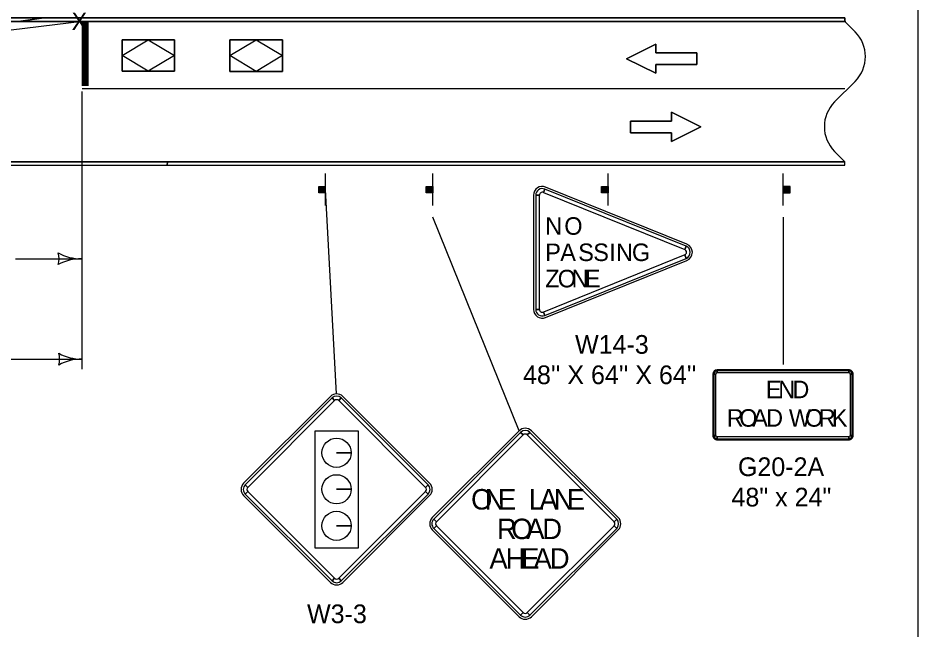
# Model space of a CAD drawing. Extents: x -2134934 to -2122394, y -2140205 to -2137036.
# Drawn here: x -2132569 to -2131799, y -2138065 to -2137542 of the extents above; entities that cross this region are included whole.
import ezdxf

# ---------------------------------------------------------------- set-up
doc = ezdxf.new("R2010")
doc.units = 0
for name, color, linetype in [('Barrier', 7, 'Continuous'), ('BridgeSuperStructureExisting', 7, 'Continuous'), ('Default', 7, 'Continuous'), ('DsnShtPlotIdentification', 7, 'Continuous'), ('DsnShtPlotShape', 7, 'Continuous'), ('dsnTextFinalPlan', 7, 'Continuous')]:
    doc.layers.add(name, color=color, linetype=linetype)

msp = doc.modelspace()

# ---------------------------------------------------------------- linework, layer by layer
at = {"layer": 'Barrier'}
for p, q in [((-2132119.84, -2137691.45), (-2132118.67, -2137688.56)), ((-2131997.15, -2137735.69), (-2132117.97, -2137686.82)), ((-2132128.28, -2137693.77), (-2132128.28, -2137791.52)), ((-2132126.41, -2137693.77), (-2132123.28, -2137693.77)), ((-2131997.85, -2137737.43), (-2131999.02, -2137740.33)), ((-2132117.97, -2137798.48), (-2131997.15, -2137749.6)), ((-2131999.02, -2137744.96), (-2131997.85, -2137747.86)), ((-2132123.28, -2137791.52), (-2132126.41, -2137791.52)), ((-2132118.67, -2137796.74), (-2132119.84, -2137793.84)), ((-2131858.66, -2137843.14), (-2131971.16, -2137843.14)), ((-2131971.16, -2137845.64), (-2131971.16, -2137844.08)), ((-2131858.66, -2137844.08), (-2131858.66, -2137845.64)), ((-2131974.91, -2137846.89), (-2131974.91, -2137899.39)), ((-2131973.97, -2137846.89), (-2131972.41, -2137846.89)), ((-2131857.41, -2137846.89), (-2131855.85, -2137846.89)), ((-2131854.91, -2137899.39), (-2131854.91, -2137846.89)), ((-2132301.99, -2137865.99), (-2132376.24, -2137940.23)), ((-2132300.66, -2137867.31), (-2132298.45, -2137869.52)), ((-2132294.92, -2137869.52), (-2132292.71, -2137867.31)), ((-2132217.14, -2137940.23), (-2132291.38, -2137865.99)), ((-2132140.68, -2137895.4), (-2132214.93, -2137969.64)), ((-2132139.36, -2137896.72), (-2132137.15, -2137898.93)), ((-2132133.61, -2137898.93), (-2132131.4, -2137896.72)), ((-2132055.83, -2137969.64), (-2132130.08, -2137895.4)), ((-2131972.41, -2137899.39), (-2131973.97, -2137899.39)), ((-2131971.16, -2137902.2), (-2131971.16, -2137900.64)), ((-2131971.16, -2137903.14), (-2131858.66, -2137903.14)), ((-2131858.66, -2137900.64), (-2131858.66, -2137902.2)), ((-2131855.85, -2137899.39), (-2131857.41, -2137899.39)), ((-2132284.28, -2137914.21), (-2132296.78, -2137914.21)), ((-2132296.78, -2137914.21), (-2132284.28, -2137914.21)), ((-2132372.7, -2137943.77), (-2132374.91, -2137941.56)), ((-2132218.46, -2137941.56), (-2132220.67, -2137943.77)), ((-2132376.24, -2137950.84), (-2132301.99, -2138025.09)), ((-2132374.91, -2137949.51), (-2132372.7, -2137947.3)), ((-2132284.28, -2137945.46), (-2132296.78, -2137945.46)), ((-2132296.78, -2137945.46), (-2132284.28, -2137945.46)), ((-2132291.38, -2138025.09), (-2132217.14, -2137950.84)), ((-2132220.67, -2137947.3), (-2132218.46, -2137949.51)), ((-2132211.4, -2137973.18), (-2132213.6, -2137970.97)), ((-2132057.16, -2137970.97), (-2132059.37, -2137973.18)), ((-2132284.28, -2137976.71), (-2132296.78, -2137976.71)), ((-2132296.78, -2137976.71), (-2132284.28, -2137976.71)), ((-2132214.93, -2137980.25), (-2132140.68, -2138054.5)), ((-2132213.6, -2137978.92), (-2132211.4, -2137976.71)), ((-2132130.08, -2138054.5), (-2132055.83, -2137980.25)), ((-2132059.37, -2137976.71), (-2132057.16, -2137978.92)), ((-2132298.45, -2138021.55), (-2132300.66, -2138023.76)), ((-2132292.71, -2138023.76), (-2132294.92, -2138021.55)), ((-2132137.15, -2138050.96), (-2132139.36, -2138053.17)), ((-2132131.4, -2138053.17), (-2132133.61, -2138050.96))]:
    msp.add_line(p, q, dxfattribs=at)
for points in [[(-2131997.85, -2137737.43), (-2132118.67, -2137688.56), (-2132119.84, -2137691.45), (-2131999.02, -2137740.33), (-2131997.85, -2137737.43)], [(-2132126.41, -2137693.77), (-2132126.41, -2137791.52), (-2132123.28, -2137791.52), (-2132123.28, -2137693.77), (-2132126.41, -2137693.77)], [(-2132118.67, -2137796.74), (-2131997.85, -2137747.86), (-2131999.02, -2137744.96), (-2132119.84, -2137793.84), (-2132118.67, -2137796.74)], [(-2131858.66, -2137844.08), (-2131971.16, -2137844.08), (-2131971.16, -2137845.64), (-2131858.66, -2137845.64), (-2131858.66, -2137844.08)], [(-2131973.97, -2137846.89), (-2131973.97, -2137899.39), (-2131972.41, -2137899.39), (-2131972.41, -2137846.89), (-2131973.97, -2137846.89)], [(-2131855.85, -2137899.39), (-2131855.85, -2137846.89), (-2131857.41, -2137846.89), (-2131857.41, -2137899.39), (-2131855.85, -2137899.39)], [(-2132300.66, -2137867.31), (-2132374.91, -2137941.56), (-2132372.7, -2137943.77), (-2132298.45, -2137869.52), (-2132300.66, -2137867.31)], [(-2132218.46, -2137941.56), (-2132292.71, -2137867.31), (-2132294.92, -2137869.52), (-2132220.67, -2137943.77), (-2132218.46, -2137941.56)], [(-2132277.96, -2137895.59), (-2132315.42, -2137895.59), (-2132315.42, -2137995.48), (-2132277.96, -2137995.48), (-2132277.96, -2137895.59)], [(-2132139.36, -2137896.72), (-2132213.6, -2137970.97), (-2132211.4, -2137973.18), (-2132137.15, -2137898.93), (-2132139.36, -2137896.72)], [(-2132057.16, -2137970.97), (-2132131.4, -2137896.72), (-2132133.61, -2137898.93), (-2132059.37, -2137973.18), (-2132057.16, -2137970.97)], [(-2131971.16, -2137902.2), (-2131858.66, -2137902.2), (-2131858.66, -2137900.64), (-2131971.16, -2137900.64), (-2131971.16, -2137902.2)], [(-2132374.91, -2137949.51), (-2132300.66, -2138023.76), (-2132298.45, -2138021.55), (-2132372.7, -2137947.3), (-2132374.91, -2137949.51)], [(-2132292.71, -2138023.76), (-2132218.46, -2137949.51), (-2132220.67, -2137947.3), (-2132294.92, -2138021.55), (-2132292.71, -2138023.76)], [(-2132213.6, -2137978.92), (-2132139.36, -2138053.17), (-2132137.15, -2138050.96), (-2132211.4, -2137976.71), (-2132213.6, -2137978.92)], [(-2132131.4, -2138053.17), (-2132057.16, -2137978.92), (-2132059.37, -2137976.71), (-2132133.61, -2138050.96), (-2132131.4, -2138053.17)]]:
    msp.add_lwpolyline(points, close=True, dxfattribs=at)
for centre in [(-2132296.78, -2137914.21), (-2132296.78, -2137945.46), (-2132296.78, -2137976.71)]:
    msp.add_circle(centre, 12.5, dxfattribs=at)
for centre, radius, start, end in [((-2132120.78, -2137693.77), 7.5, 67.97571, 179.99985), ((-2132120.78, -2137693.77), 5.62, 67.97571, 179.99985), ((-2132120.78, -2137693.77), 2.5, 67.97571, 179.99985), ((-2131999.96, -2137742.65), 7.5, 292.02456, 67.97598), ((-2131999.96, -2137742.65), 2.5, 292.02456, 67.97541), ((-2131999.96, -2137742.65), 5.62, 292.02456, 67.97541), ((-2132120.78, -2137791.52), 7.5, 179.99985, 292.02456), ((-2132120.78, -2137791.52), 5.62, 179.99985, 292.02456), ((-2132120.78, -2137791.52), 2.5, 179.99985, 292.02456), ((-2131971.16, -2137846.89), 3.75, 90.00021, 179.99985), ((-2131971.16, -2137846.89), 2.81, 90.00021, 179.99985), ((-2131858.66, -2137846.89), 3.75, 0, 90.00021), ((-2131858.66, -2137846.89), 2.81, 0, 90.00021), ((-2131971.16, -2137846.89), 1.25, 90.00021, 179.99985), ((-2131858.66, -2137846.89), 1.25, 0, 90.00021), ((-2132296.69, -2137871.29), 7.5, 44.99999, 134.99974), ((-2132296.69, -2137871.29), 5.62, 44.99999, 134.99974), ((-2132296.69, -2137871.29), 2.5, 44.99999, 134.99974), ((-2132135.38, -2137900.7), 7.5, 44.99999, 134.99974), ((-2132135.38, -2137900.7), 5.62, 44.99999, 134.99974), ((-2132135.38, -2137900.7), 2.5, 44.99999, 134.99974), ((-2131971.16, -2137899.39), 3.75, 179.99985, 270.00006), ((-2131971.16, -2137899.39), 2.81, 179.99985, 270.00006), ((-2131971.16, -2137899.39), 1.25, 179.99985, 270.00006), ((-2131858.66, -2137899.39), 3.75, 270.00006, 0.00027), ((-2131858.66, -2137899.39), 2.81, 270.00006, 0.00027), ((-2131858.66, -2137899.39), 1.25, 270.00006, 0.00027), ((-2132370.93, -2137945.54), 7.5, 134.99974, 224.99995), ((-2132370.93, -2137945.54), 5.62, 134.99974, 224.99995), ((-2132370.93, -2137945.54), 2.5, 134.99974, 224.99995), ((-2132222.44, -2137945.54), 2.5, 315.00016, 44.9998), ((-2132222.44, -2137945.54), 5.62, 315.00016, 44.9998), ((-2132222.44, -2137945.54), 7.5, 315.00016, 44.9998), ((-2132209.63, -2137974.95), 7.5, 134.99974, 224.99995), ((-2132209.63, -2137974.95), 5.62, 134.99974, 224.99995), ((-2132209.63, -2137974.95), 2.5, 134.99974, 224.99995), ((-2132061.14, -2137974.95), 2.5, 315.00016, 44.9998), ((-2132061.14, -2137974.95), 5.62, 315.00016, 44.9998), ((-2132061.14, -2137974.95), 7.5, 315.00016, 44.9998), ((-2132296.69, -2138019.78), 7.5, 224.99995, 315.00016), ((-2132296.69, -2138019.78), 5.62, 224.99995, 315.00016), ((-2132296.69, -2138019.78), 2.5, 224.99995, 315.00016), ((-2132135.38, -2138049.19), 2.5, 224.99995, 315.00016), ((-2132135.38, -2138049.19), 7.5, 224.99995, 315.00016), ((-2132135.38, -2138049.19), 5.62, 224.99995, 315.00016)]:
    msp.add_arc(centre, radius, start, end, dxfattribs=at)
at = {"layer": 'BridgeSuperStructureExisting'}
for p, q in [((-2131861.99, -2137545.16), (-2133174.44, -2137545.16)), ((-2132514.45, -2137545.16), (-2133004.39, -2137605.15)), ((-2132514.45, -2137545.16), (-2132514.45, -2137600.16)), ((-2132513.45, -2137545.16), (-2132513.45, -2137600.16)), ((-2132512.45, -2137545.16), (-2132512.45, -2137600.16)), ((-2132511.45, -2137545.16), (-2132511.45, -2137600.16)), ((-2132510.45, -2137545.16), (-2132510.45, -2137600.16)), ((-2132509.45, -2137545.16), (-2132509.45, -2137600.16)), ((-2131853.21, -2137553.94), (-2131861.99, -2137545.16)), ((-2131853.2, -2137553.95), (-2131861.99, -2137545.16)), ((-2132480.28, -2137587.78), (-2132480.28, -2137560.78)), ((-2132480.28, -2137560.78), (-2132435.28, -2137560.78)), ((-2132480.28, -2137587.78), (-2132480.28, -2137560.78)), ((-2132480.28, -2137560.78), (-2132435.28, -2137560.78)), ((-2132435.28, -2137560.78), (-2132480.28, -2137560.78)), ((-2132480.28, -2137560.78), (-2132480.28, -2137587.78)), ((-2132435.28, -2137587.78), (-2132435.28, -2137560.78)), ((-2132435.28, -2137560.78), (-2132435.28, -2137587.78)), ((-2132435.28, -2137587.78), (-2132435.28, -2137560.78)), ((-2132388.09, -2137587.86), (-2132388.09, -2137560.86)), ((-2132388.09, -2137560.86), (-2132343.09, -2137560.86)), ((-2132388.09, -2137587.86), (-2132388.09, -2137560.86)), ((-2132388.09, -2137560.86), (-2132343.09, -2137560.86)), ((-2132343.09, -2137560.86), (-2132388.09, -2137560.86)), ((-2132388.09, -2137560.86), (-2132388.09, -2137587.86)), ((-2132343.09, -2137587.86), (-2132343.09, -2137560.86)), ((-2132343.09, -2137560.86), (-2132343.09, -2137587.86)), ((-2132343.09, -2137587.86), (-2132343.09, -2137560.86)), ((-2132480.28, -2137587.78), (-2132435.28, -2137587.78)), ((-2132435.28, -2137587.78), (-2132480.28, -2137587.78)), ((-2132480.28, -2137587.78), (-2132435.28, -2137587.78)), ((-2132388.09, -2137587.86), (-2132343.09, -2137587.86)), ((-2132343.09, -2137587.86), (-2132388.09, -2137587.86)), ((-2132388.09, -2137587.86), (-2132343.09, -2137587.86)), ((-2131870.78, -2137613.94), (-2131853.21, -2137596.37)), ((-2131870.78, -2137613.95), (-2131853.2, -2137596.37)), ((-2132514.45, -2137842.77), (-2132514.45, -2137605.16)), ((-2131861.99, -2137665.16), (-2131870.78, -2137656.37)), ((-2131861.99, -2137665.16), (-2131870.78, -2137656.37)), ((-2133364.44, -2137665.16), (-2131861.99, -2137665.16)), ((-2132306.28, -2137702.66), (-2132306.28, -2137675.16)), ((-2132214.45, -2137702.66), (-2132214.45, -2137675.16)), ((-2132064.45, -2137702.66), (-2132064.45, -2137675.16)), ((-2131914.64, -2137702.66), (-2131914.64, -2137675.16)), ((-2132311.61, -2137691.8), (-2132311.61, -2137686.21)), ((-2132311.29, -2137686.21), (-2132311.29, -2137691.8)), ((-2132311.07, -2137691.8), (-2132311.07, -2137686.21)), ((-2132310.75, -2137686.21), (-2132310.75, -2137691.8)), ((-2132310.52, -2137691.8), (-2132310.54, -2137686.21)), ((-2132310.11, -2137686.21), (-2132310.09, -2137691.8)), ((-2132309.89, -2137691.8), (-2132309.89, -2137686.21)), ((-2132309.45, -2137686.21), (-2132309.45, -2137691.8)), ((-2132309.08, -2137691.8), (-2132309.08, -2137686.21)), ((-2132308.76, -2137686.21), (-2132308.74, -2137691.8)), ((-2132308.54, -2137691.8), (-2132308.54, -2137686.21)), ((-2132308.27, -2137686.21), (-2132308.27, -2137691.8)), ((-2132307.94, -2137691.8), (-2132307.94, -2137686.21)), ((-2132307.73, -2137686.21), (-2132307.73, -2137691.8)), ((-2132307.5, -2137691.8), (-2132307.5, -2137686.21)), ((-2132307.24, -2137686.21), (-2132307.24, -2137691.8)), ((-2132306.98, -2137691.8), (-2132306.98, -2137686.21)), ((-2132306.7, -2137686.21), (-2132306.7, -2137691.8)), ((-2132296.69, -2137863.79), (-2132306.28, -2137688.91)), ((-2132219.77, -2137691.8), (-2132219.77, -2137686.21)), ((-2132219.45, -2137686.21), (-2132219.45, -2137691.8)), ((-2132219.23, -2137691.8), (-2132219.23, -2137686.21)), ((-2132218.91, -2137686.21), (-2132218.91, -2137691.8)), ((-2132218.69, -2137691.8), (-2132218.7, -2137686.21)), ((-2132218.27, -2137686.21), (-2132218.25, -2137691.8)), ((-2132218.05, -2137691.8), (-2132218.05, -2137686.21)), ((-2132217.62, -2137686.21), (-2132217.62, -2137691.8)), ((-2132217.24, -2137691.8), (-2132217.24, -2137686.21)), ((-2132216.92, -2137686.21), (-2132216.9, -2137691.8)), ((-2132216.7, -2137691.8), (-2132216.7, -2137686.21)), ((-2132216.43, -2137686.21), (-2132216.43, -2137691.8)), ((-2132216.1, -2137691.8), (-2132216.1, -2137686.21)), ((-2132215.89, -2137686.21), (-2132215.89, -2137691.8)), ((-2132215.67, -2137691.8), (-2132215.67, -2137686.21)), ((-2132215.4, -2137686.21), (-2132215.4, -2137691.8)), ((-2132215.14, -2137691.8), (-2132215.14, -2137686.21)), ((-2132214.86, -2137686.21), (-2132214.86, -2137691.8)), ((-2132069.77, -2137691.8), (-2132069.77, -2137686.21)), ((-2132069.45, -2137686.21), (-2132069.45, -2137691.8)), ((-2132069.23, -2137691.8), (-2132069.23, -2137686.21)), ((-2132068.91, -2137686.21), (-2132068.91, -2137691.8)), ((-2132068.69, -2137691.8), (-2132068.7, -2137686.21)), ((-2132068.27, -2137686.21), (-2132068.25, -2137691.8)), ((-2132068.05, -2137691.8), (-2132068.05, -2137686.21)), ((-2132067.62, -2137686.21), (-2132067.62, -2137691.8)), ((-2132067.24, -2137691.8), (-2132067.24, -2137686.21)), ((-2132066.92, -2137686.21), (-2132066.9, -2137691.8)), ((-2132066.7, -2137691.8), (-2132066.7, -2137686.21)), ((-2132066.43, -2137686.21), (-2132066.43, -2137691.8)), ((-2132066.1, -2137691.8), (-2132066.1, -2137686.21)), ((-2132065.89, -2137686.21), (-2132065.89, -2137691.8)), ((-2132065.67, -2137691.8), (-2132065.67, -2137686.21)), ((-2132065.4, -2137686.21), (-2132065.4, -2137691.8)), ((-2132065.14, -2137691.8), (-2132065.14, -2137686.21)), ((-2132064.86, -2137686.21), (-2132064.86, -2137691.8)), ((-2131914.22, -2137686.21), (-2131914.22, -2137691.8)), ((-2131913.94, -2137691.8), (-2131913.94, -2137686.21)), ((-2131913.68, -2137686.21), (-2131913.68, -2137691.8)), ((-2131913.42, -2137691.8), (-2131913.42, -2137686.21)), ((-2131913.19, -2137686.21), (-2131913.19, -2137691.8)), ((-2131912.99, -2137691.8), (-2131912.99, -2137686.21)), ((-2131912.65, -2137686.21), (-2131912.65, -2137691.8)), ((-2131912.39, -2137691.8), (-2131912.39, -2137686.21)), ((-2131912.16, -2137686.21), (-2131912.18, -2137691.8)), ((-2131911.84, -2137691.8), (-2131911.84, -2137686.21)), ((-2131911.47, -2137686.21), (-2131911.47, -2137691.8)), ((-2131911.04, -2137691.8), (-2131911.04, -2137686.21)), ((-2131910.81, -2137686.21), (-2131910.83, -2137691.8)), ((-2131910.4, -2137691.8), (-2131910.38, -2137686.21)), ((-2131910.17, -2137686.21), (-2131910.17, -2137691.8)), ((-2131909.85, -2137691.8), (-2131909.85, -2137686.21)), ((-2131909.63, -2137686.21), (-2131909.63, -2137691.8)), ((-2131909.31, -2137691.8), (-2131909.31, -2137686.21)), ((-2132140.68, -2137895.4), (-2132214.45, -2137712.66)), ((-2131914.45, -2137838.71), (-2131914.45, -2137712.66)), ((-2132571.38, -2137748.23), (-2132514.94, -2137748.23)), ((-2132739.17, -2137834.09), (-2132514.45, -2137834.09))]:
    msp.add_line(p, q, dxfattribs=at)
for points in [[(-2131988.74, -2137582), (-2131988.74, -2137572), (-2132023.74, -2137572), (-2132023.74, -2137564.5), (-2132048.74, -2137577), (-2132023.74, -2137589.5), (-2132023.74, -2137582)], [(-2132045.26, -2137630.33), (-2132045.26, -2137640.33), (-2132010.26, -2137640.33), (-2132010.26, -2137647.83), (-2131985.26, -2137635.33), (-2132010.26, -2137622.83), (-2132010.26, -2137630.33)], [(-2132306.38, -2137686.21), (-2132306.38, -2137691.84), (-2132312, -2137691.84), (-2132312, -2137686.21)], [(-2132214.54, -2137686.21), (-2132214.54, -2137691.84), (-2132220.17, -2137691.84), (-2132220.17, -2137686.21)], [(-2132064.54, -2137686.21), (-2132064.54, -2137691.84), (-2132070.17, -2137691.84), (-2132070.17, -2137686.21)], [(-2131914.54, -2137686.21), (-2131914.54, -2137691.84), (-2131908.92, -2137691.84), (-2131908.92, -2137686.21)]]:
    msp.add_lwpolyline(points, close=True, dxfattribs=at)
for points in [[(-2132023.74, -2137582), (-2132023.74, -2137589.5), (-2132048.74, -2137577), (-2132023.74, -2137564.5), (-2132023.74, -2137572), (-2131988.74, -2137572), (-2131988.74, -2137582), (-2132023.74, -2137582)], [(-2132010.26, -2137630.33), (-2132010.26, -2137622.83), (-2131985.26, -2137635.33), (-2132010.26, -2137647.83), (-2132010.26, -2137640.33), (-2132045.26, -2137640.33), (-2132045.26, -2137630.33), (-2132010.26, -2137630.33)]]:
    msp.add_lwpolyline(points, dxfattribs=at)
for centre, radius, start, end in [((-2131874.42, -2137575.16), 30, 315, 45), ((-2131874.42, -2137575.16), 30, 315, 45), ((-2131849.56, -2137635.16), 30, 135, 225), ((-2131849.56, -2137635.16), 30, 135, 225), ((-2132550.57, -2137748.23), 16.42, 342.26665, 17.73335), ((-2132514.94, -2137705.73), 42.5, 241.92751, 270), ((-2132514.94, -2137790.73), 42.5, 90, 118.07249)]:
    msp.add_arc(centre, radius, start, end, dxfattribs=at)
at = {"layer": 'Default'}
msp.add_lwpolyline([(-2134934.44, -2137035.95), (-2131799.45, -2137035.95), (-2131799.45, -2139045.94), (-2134934.44, -2139045.94)], close=True, dxfattribs=at)
at = {"layer": 'DsnShtPlotIdentification'}
for p, q in [((-2132547.01, -2137542.16), (-2132860.67, -2137542.16)), ((-2132547.01, -2137542.16), (-2132568.69, -2137545.16)), ((-2132568.69, -2137545.16), (-2132547.01, -2137542.16)), ((-2131861.99, -2137542.16), (-2132547.01, -2137542.16)), ((-2131861.99, -2137542.16), (-2131861.99, -2137545.16)), ((-2131861.99, -2137545.16), (-2131861.99, -2137542.16)), ((-2132861.64, -2137545.16), (-2132568.69, -2137545.16)), ((-2132568.69, -2137545.16), (-2132514.45, -2137545.16)), ((-2132509.45, -2137545.16), (-2131861.99, -2137545.16)), ((-2131861.95, -2137602.66), (-2132514.45, -2137602.66)), ((-2133364.44, -2137665.16), (-2131861.99, -2137665.16)), ((-2133364.44, -2137665.16), (-2131861.99, -2137665.16)), ((-2132441.05, -2137665.16), (-2132714.94, -2137665.16)), ((-2132442.06, -2137668.16), (-2132441.05, -2137665.16)), ((-2132441.05, -2137665.16), (-2132442.06, -2137668.16)), ((-2131861.99, -2137665.16), (-2132441.05, -2137665.16)), ((-2131861.99, -2137668.16), (-2131861.99, -2137665.16)), ((-2131861.99, -2137668.16), (-2131861.99, -2137665.16)), ((-2133364.44, -2137668.16), (-2131861.99, -2137668.16)), ((-2132714.94, -2137668.16), (-2132442.06, -2137668.16)), ((-2132442.06, -2137668.16), (-2131861.99, -2137668.16))]:
    msp.add_line(p, q, dxfattribs=at)
for points in [[(-2133174.44, -2137542.16), (-2131861.99, -2137542.16)], [(-2133174.44, -2137545.16), (-2131861.99, -2137545.16)], [(-2133173.75, -2137545.16), (-2131861.29, -2137545.16)], [(-2132514.45, -2137545.16), (-2132513.45, -2137545.16), (-2132512.45, -2137545.16)], [(-2132512.45, -2137545.16), (-2132511.45, -2137545.16), (-2132510.45, -2137545.16), (-2132509.45, -2137545.16)]]:
    msp.add_lwpolyline(points, dxfattribs=at)
at = {"layer": 'DsnShtPlotShape'}
for centre, radius, start, end in [((-2132550.08, -2137834.09), 16.42, 342.26665, 17.73335), ((-2132514.45, -2137791.59), 42.5, 241.92751, 270), ((-2132514.45, -2137876.59), 42.5, 90, 118.07249)]:
    msp.add_arc(centre, radius, start, end, dxfattribs=at)
at = {"layer": 'dsnTextFinalPlan'}
for points in [[(-2132480.28, -2137574.28), (-2132457.78, -2137560.78), (-2132435.28, -2137574.28), (-2132457.78, -2137587.78)], [(-2132388.09, -2137574.36), (-2132365.59, -2137560.86), (-2132343.09, -2137574.36), (-2132365.59, -2137587.86)]]:
    msp.add_lwpolyline(points, close=True, dxfattribs=at)

# ---------------------------------------------------------------- texts
at = {"layer": 'Barrier'}
for s, height, p in [('N', 15, (-2132118.31, -2137727.65)), ('O', 15, (-2132101.97, -2137727.65)), ('P', 15, (-2132118.31, -2137750.15)), ('A', 15, (-2132105.42, -2137750.15)), ('S', 15, (-2132090.07, -2137750.15)), ('S', 15, (-2132077.18, -2137750.15)), ('I', 15, (-2132063.59, -2137750.15)), ('N', 15, (-2132057.73, -2137750.15)), ('G', 15, (-2132044.13, -2137750.15)), ('Z', 15, (-2132118.31, -2137772.65)), ('O', 15, (-2132107.58, -2137772.65)), ('N', 15, (-2132095.75, -2137772.65)), ('E', 15, (-2132084.38, -2137772.65)), ('W14-3', 16, (-2132092.77, -2137829.48)), ("48'' X 64'' X 64''", 16, (-2132137.26, -2137855.47)), ('E', 15, (-2131929.58, -2137867.51)), ('N', 15, (-2131918.96, -2137867.51)), ('D', 15, (-2131906.88, -2137867.51)), ('R', 15, (-2131963.05, -2137891.89)), ('O', 15, (-2131952.36, -2137891.89)), ('A', 15, (-2131941.21, -2137891.89)), ('D', 15, (-2131929.35, -2137891.89)), ('W', 15, (-2131909.9, -2137891.89)), ('O', 15, (-2131896.16, -2137891.89)), ('R', 15, (-2131884.4, -2137891.89)), ('K', 15, (-2131873.1, -2137891.89)), ('G20-2A', 16, (-2131953.44, -2137934.14)), ('48" x 24"', 16, (-2131958.97, -2137960.14)), ('O', 17.5, (-2132181.67, -2137962.76)), ('N', 17.5, (-2132169.89, -2137962.76)), ('E', 17.5, (-2132158.66, -2137962.76)), ('L', 17.5, (-2132132.41, -2137962.76)), ('A', 17.5, (-2132123.22, -2137962.76)), ('N', 17.5, (-2132110.95, -2137962.76)), ('E', 17.5, (-2132099.72, -2137962.76)), ('R', 17.5, (-2132159.56, -2137988.07)), ('O', 17.5, (-2132147.27, -2137988.07)), ('A', 17.5, (-2132134.43, -2137988.07)), ('D', 17.5, (-2132120.78, -2137988.07)), ('A', 17.5, (-2132166, -2138013.38)), ('H', 17.5, (-2132152.13, -2138013.38)), ('E', 17.5, (-2132138.91, -2138013.38)), ('A', 17.5, (-2132128.2, -2138013.38)), ('D', 17.5, (-2132114.34, -2138013.38)), ('W3-3', 16, (-2132321.98, -2138060))]:
    msp.add_text(s, height=height, dxfattribs=at).set_placement(p)
at = {"layer": 'BridgeSuperStructureExisting'}
msp.add_text('X', height=15, dxfattribs=at).set_placement((-2132523.45, -2137552.51))

doc.saveas('drawing.dxf')
